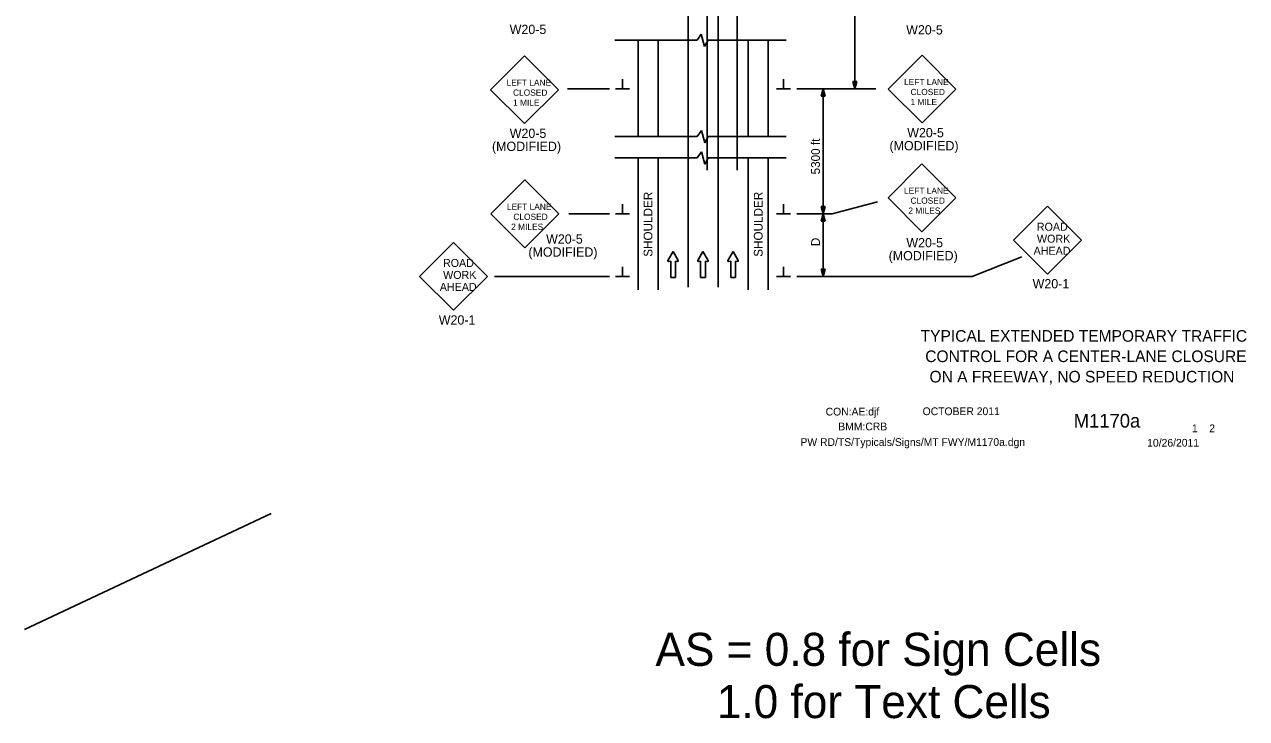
# Model space of a CAD drawing. Extents: x 16450 to 18482, y 7002 to 8333.
# Drawn here: x 16450 to 17427, y 7002 to 7557 of the extents above; entities that cross this region are included whole.
import ezdxf

# ---------------------------------------------------------------- set-up
doc = ezdxf.new("R2010")
doc.units = 0
for name, color, linetype in [('ALI_LEGAL_EX', 7, 'Continuous'), ('BORDER', 7, 'Continuous'), ('BORDER_SIGNAL_WO', 7, 'Continuous'), ('MT_SCRATCH_LEVEL_E', 7, 'Continuous'), ('PAVT_EDGE_EX', 7, 'Continuous'), ('TRAFFIC_SIGNS_PR', 7, 'Continuous'), ('TYPICAL_TEXT_DIMEN_PR', 7, 'Continuous')]:
    doc.layers.add(name, color=color, linetype=linetype)

msp = doc.modelspace()

# ---------------------------------------------------------------- linework, layer by layer
at = {"layer": 'ALI_LEGAL_EX'}
for p, q in [((16980.68, 8333.08), (16980.68, 7514.94)), ((17004.68, 8333.08), (17004.68, 7514.94)), ((16995.95, 8258.85), (16995.95, 7440.72)), ((17019.95, 8258.85), (17019.95, 7440.72)), ((16980.68, 7467.53), (16980.68, 7544.69)), ((17004.68, 7467.53), (17004.68, 7544.69)), ((16980.68, 7347.09), (16980.68, 7527.9)), ((17004.68, 7347.09), (17004.68, 7527.9))]:
    msp.add_line(p, q, dxfattribs=at)
for points in [[(16980.68, 7467.53), (16980.68, 7492.53)], [(17004.68, 7467.53), (17004.68, 7492.53)], [(16980.68, 7369.59), (16980.68, 7394.59)], [(17004.68, 7369.59), (17004.68, 7394.59)]]:
    msp.add_lwpolyline(points, dxfattribs=at)
at = {"layer": 'MT_SCRATCH_LEVEL_E'}
for p, q in [((16968.68, 7375.46), (16964.56, 7368.22)), ((16972.82, 7368.22), (16968.68, 7375.46)), ((16992.58, 7375.46), (16988.47, 7368.22)), ((16996.73, 7368.22), (16992.58, 7375.46)), ((17016.63, 7375.46), (17012.52, 7368.22)), ((17020.78, 7368.22), (17016.63, 7375.46)), ((16965.05, 7367.54), (16966.82, 7367.85)), ((16966.82, 7367.85), (16966.82, 7354.6)), ((16970.57, 7354.6), (16970.57, 7367.85)), ((16970.57, 7367.85), (16972.34, 7367.54)), ((16988.95, 7367.54), (16990.73, 7367.85)), ((16990.73, 7367.85), (16990.73, 7354.6)), ((16994.47, 7354.6), (16994.47, 7367.85)), ((16994.47, 7367.85), (16996.25, 7367.54)), ((17013, 7367.54), (17014.78, 7367.85)), ((17014.78, 7367.85), (17014.78, 7354.6)), ((17018.52, 7354.6), (17018.52, 7367.85)), ((17018.52, 7367.85), (17020.3, 7367.54)), ((16966.82, 7354.6), (16970.57, 7354.6)), ((16990.73, 7354.6), (16994.47, 7354.6)), ((17014.78, 7354.6), (17018.52, 7354.6))]:
    msp.add_line(p, q, dxfattribs=at)
for centre, start, end in [((16964.97, 7368), 150.42484, 279.96381), ((16972.41, 7368), 260.03619, 29.77312), ((16988.88, 7368), 150.42484, 279.96381), ((16996.32, 7368), 260.03619, 29.77312), ((17012.93, 7368), 150.42484, 279.96381), ((17020.37, 7368), 260.03619, 29.77312)]:
    msp.add_arc(centre, 0.463, start, end, dxfattribs=at)
at = {"layer": 'PAVT_EDGE_EX'}
for p, q in [((16940.68, 7544.69), (16940.68, 7467.55)), ((16956.68, 7544.69), (16956.68, 7467.55)), ((17028.68, 7544.7), (17028.68, 7467.55)), ((17044.68, 7544.7), (17044.68, 7467.55)), ((16940.68, 7450.41), (16940.68, 7344.83)), ((16956.68, 7450.41), (16956.68, 7344.83)), ((17028.68, 7450.41), (17028.68, 7344.83)), ((17044.68, 7450.41), (17044.68, 7344.83))]:
    msp.add_line(p, q, dxfattribs=at)
at = {"layer": 'TRAFFIC_SIGNS_PR'}
for p, q in [((16849.8, 7532.12), (16822.64, 7504.97)), ((16876.95, 7504.97), (16849.8, 7532.12)), ((17167.8, 7532.64), (17140.65, 7505.49)), ((17194.95, 7505.49), (17167.8, 7532.64)), ((16822.64, 7504.97), (16849.8, 7477.81)), ((16849.8, 7477.81), (16876.95, 7504.97)), ((17140.65, 7505.49), (17167.8, 7478.34)), ((17167.8, 7478.34), (17194.95, 7505.49)), ((17167.78, 7445.69), (17140.62, 7418.53)), ((17194.93, 7418.53), (17167.78, 7445.69)), ((16850.05, 7432.8), (16822.89, 7405.65)), ((16877.2, 7405.65), (16850.05, 7432.8)), ((17140.62, 7418.53), (17167.78, 7391.38)), ((17167.78, 7391.38), (17194.93, 7418.53)), ((17268.11, 7411.76), (17240.96, 7384.61)), ((17295.26, 7384.61), (17268.11, 7411.76)), ((16822.89, 7405.65), (16850.05, 7378.5)), ((16850.05, 7378.5), (16877.2, 7405.65)), ((16793.07, 7382.79), (16765.91, 7355.64)), ((16820.22, 7355.64), (16793.07, 7382.79)), ((17240.96, 7384.61), (17268.11, 7357.45)), ((17268.11, 7357.45), (17295.26, 7384.61)), ((16765.91, 7355.64), (16793.07, 7328.48)), ((16793.07, 7328.48), (16820.22, 7355.64))]:
    msp.add_line(p, q, dxfattribs=at)
at = {"layer": 'TYPICAL_TEXT_DIMEN_PR'}
for p, q in [((17114.11, 7788.09), (17114.11, 7505.59)), ((16991.19, 7549.49), (16987.94, 7544.69)), ((16993.93, 7539.55), (16991.19, 7549.49)), ((16987.94, 7544.69), (16921.99, 7544.69)), ((16996.67, 7544.69), (16993.93, 7539.55)), ((17059.01, 7544.69), (16996.67, 7544.69)), ((16928.3, 7505.59), (16928.3, 7513.38)), ((17057.05, 7505.59), (17057.05, 7513.38)), ((17114.11, 7505.59), (17112.54, 7511.45)), ((17112.54, 7511.45), (17114.11, 7511.45)), ((17114.11, 7511.45), (17115.69, 7511.45)), ((17115.69, 7511.45), (17114.11, 7505.59)), ((16884.28, 7505.59), (16917.68, 7505.59)), ((16922.68, 7505.59), (16933.93, 7505.59)), ((17062.68, 7505.59), (17051.43, 7505.59)), ((17130.82, 7505.59), (17067.68, 7505.59)), ((17087.11, 7499.73), (17088.68, 7505.59)), ((17088.68, 7499.73), (17087.11, 7499.73)), ((17088.68, 7505.59), (17088.68, 7405.59)), ((17088.68, 7505.59), (17090.25, 7499.73)), ((17090.25, 7499.73), (17088.68, 7499.73)), ((16991.28, 7472.33), (16988.03, 7467.53)), ((16994.02, 7462.39), (16991.28, 7472.33)), ((16988.03, 7467.53), (16922.08, 7467.53)), ((16996.76, 7467.53), (16994.02, 7462.39)), ((17059.1, 7467.53), (16996.76, 7467.53)), ((16988.03, 7450.39), (16922.08, 7450.39)), ((16991.28, 7455.19), (16988.03, 7450.39)), ((16994.02, 7445.26), (16991.28, 7455.19)), ((16996.76, 7450.39), (16994.02, 7445.26)), ((17059.1, 7450.39), (16996.76, 7450.39)), ((16928.3, 7405.59), (16928.3, 7413.38)), ((17057.05, 7405.59), (17057.05, 7413.38)), ((17088.68, 7405.59), (17087.11, 7411.45)), ((17087.11, 7411.45), (17088.68, 7411.45)), ((17088.68, 7411.45), (17090.25, 7411.45)), ((17090.25, 7411.45), (17088.68, 7405.59)), ((17095.96, 7405.59), (17132.29, 7415.16)), ((16885.15, 7405.59), (16917.68, 7405.59)), ((16922.68, 7405.59), (16933.93, 7405.59)), ((17062.68, 7405.59), (17051.43, 7405.59)), ((17095.96, 7405.59), (17067.68, 7405.59)), ((17087.11, 7399.73), (17088.68, 7405.59)), ((17088.68, 7405.59), (17088.68, 7355.59)), ((17088.68, 7405.59), (17090.25, 7399.73)), ((17088.68, 7399.73), (17087.11, 7399.73)), ((17090.25, 7399.73), (17088.68, 7399.73)), ((16928.3, 7355.59), (16928.3, 7363.38)), ((17057.05, 7355.59), (17057.05, 7363.38)), ((17208.03, 7355.59), (17247.62, 7371.35)), ((16825.79, 7355.59), (16917.68, 7355.59)), ((16922.68, 7355.59), (16933.93, 7355.59)), ((17062.68, 7355.59), (17051.43, 7355.59)), ((17208.03, 7355.59), (17067.68, 7355.59)), ((17088.68, 7355.59), (17087.11, 7361.45)), ((17087.11, 7361.45), (17088.68, 7361.45)), ((17088.68, 7361.45), (17090.25, 7361.45)), ((17090.25, 7361.45), (17088.68, 7355.59)), ((16647.08, 7166.01), (16449.77, 7073.04))]:
    msp.add_line(p, q, dxfattribs=at)

# ---------------------------------------------------------------- texts
at = {"layer": 'BORDER'}
for s, p in [('TYPICAL EXTENDED TEMPORARY TRAFFIC', (17166.71, 7303.33)), ('CONTROL FOR A CENTER-LANE CLOSURE', (17170.4, 7287.03)), ('ON A FREEWAY, NO SPEED REDUCTION', (17173.8, 7270.73))]:
    msp.add_text(s, height=9.3, dxfattribs=at).set_placement(p)
at = {"layer": 'BORDER_SIGNAL_WO'}
for s, height, p in [('CON:AE:djf  ', 6.2, (17090.69, 7244.31)), ('    OCTOBER 2011    ', 6.2, (17159.08, 7244.59)), ('    M1170a   ', 11, (17272.86, 7234.63)), ('BMM:CRB   ', 6.2, (17100.81, 7232.42)), (' 1    2 ', 6.2, (17381.45, 7230.95)), ('PW RD/TS/Typicals/Signs/MT FWY/M1170a.dgn      ', 6.2, (17070.55, 7219.96)), ('10/26/2011    ', 6.2, (17347.93, 7219.38)), ('AS = 0.8 for Sign Cells', 26.4241, (16954.57, 7044.01)), ('     1.0 for Text Cells', 26.4241, (16954.57, 7002.22))]:
    msp.add_text(s, height=height, dxfattribs=at).set_placement(p)
at = {"layer": 'TRAFFIC_SIGNS_PR'}
for s, height, p in [('W20-5', 7.44, (16837.95, 7549.5)), ('W20-5', 7.44, (17155.12, 7549.15)), ('LEFT LANE', 5, (16835.42, 7508.12)), ('LEFT LANE', 5, (17153.43, 7508.64)), ('CLOSED', 5, (16840.63, 7500.12)), ('CLOSED', 5, (17158.64, 7500.64)), ('1 MILE', 5, (16840.62, 7492.12)), ('1 MILE', 5, (17158.63, 7492.64)), ('W20-5', 7.44, (16837.97, 7466.37)), ('W20-5', 7.44, (17155.97, 7466.9)), ('(MODIFIED)', 7.44, (16823.79, 7455.93)), ('(MODIFIED)', 7.44, (17141.79, 7456.46)), ('LEFT LANE', 5, (17153.4, 7421.69)), ('LEFT LANE', 5, (16835.67, 7408.8)), ('2 MILES', 5, (17156.86, 7405.69)), ('CLOSED', 5, (17158.61, 7413.69)), ('CLOSED', 5, (16840.88, 7400.8)), ('2 MILES', 5, (16839.13, 7392.8)), ('ROAD', 6.4, (17259.65, 7392.14)), ('W20-5', 7.44, (16867.09, 7381.82)), ('W20-5', 7.44, (17155.29, 7378.86)), ('WORK', 6.4, (17259.76, 7382.54)), ('(MODIFIED)', 7.44, (16852.91, 7371.38)), ('(MODIFIED)', 7.44, (17141.11, 7368.43)), ('AHEAD', 6.4, (17257.07, 7372.94)), ('ROAD', 6.4, (16784.61, 7363.17)), ('WORK', 6.4, (16784.72, 7353.57)), ('W20-1', 7.44, (17256.28, 7346.02)), ('AHEAD', 6.4, (16782.03, 7343.97)), ('W20-1', 7.44, (16781.23, 7317.05))]:
    msp.add_text(s, height=height, dxfattribs=at).set_placement(p)
at = {"layer": 'TYPICAL_TEXT_DIMEN_PR'}
for s, p in [('5300 ft', (17086.12, 7437.2)), ('SHOULDER', (16952.1, 7371.3)), ('SHOULDER', (17040.3, 7371.3)), ('D', (17086.12, 7379.81))]:
    msp.add_text(s, height=7, rotation=90, dxfattribs=at).set_placement(p)

doc.saveas('drawing.dxf')
